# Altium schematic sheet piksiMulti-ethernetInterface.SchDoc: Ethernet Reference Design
size Tabloid; ProjectTitle: 600-00094; ProjectRevision: B; DrawnBy: Shyam R Thillainathan; Organization: Swift Navigation; Address1: 650 Townsend St; Address2: Suite 410; Address3: San Francisco; Address4: CA 94103; DocumentNumber: 600-000XX; Revision: REV A; SheetNumber: 1; SheetTotal: 1
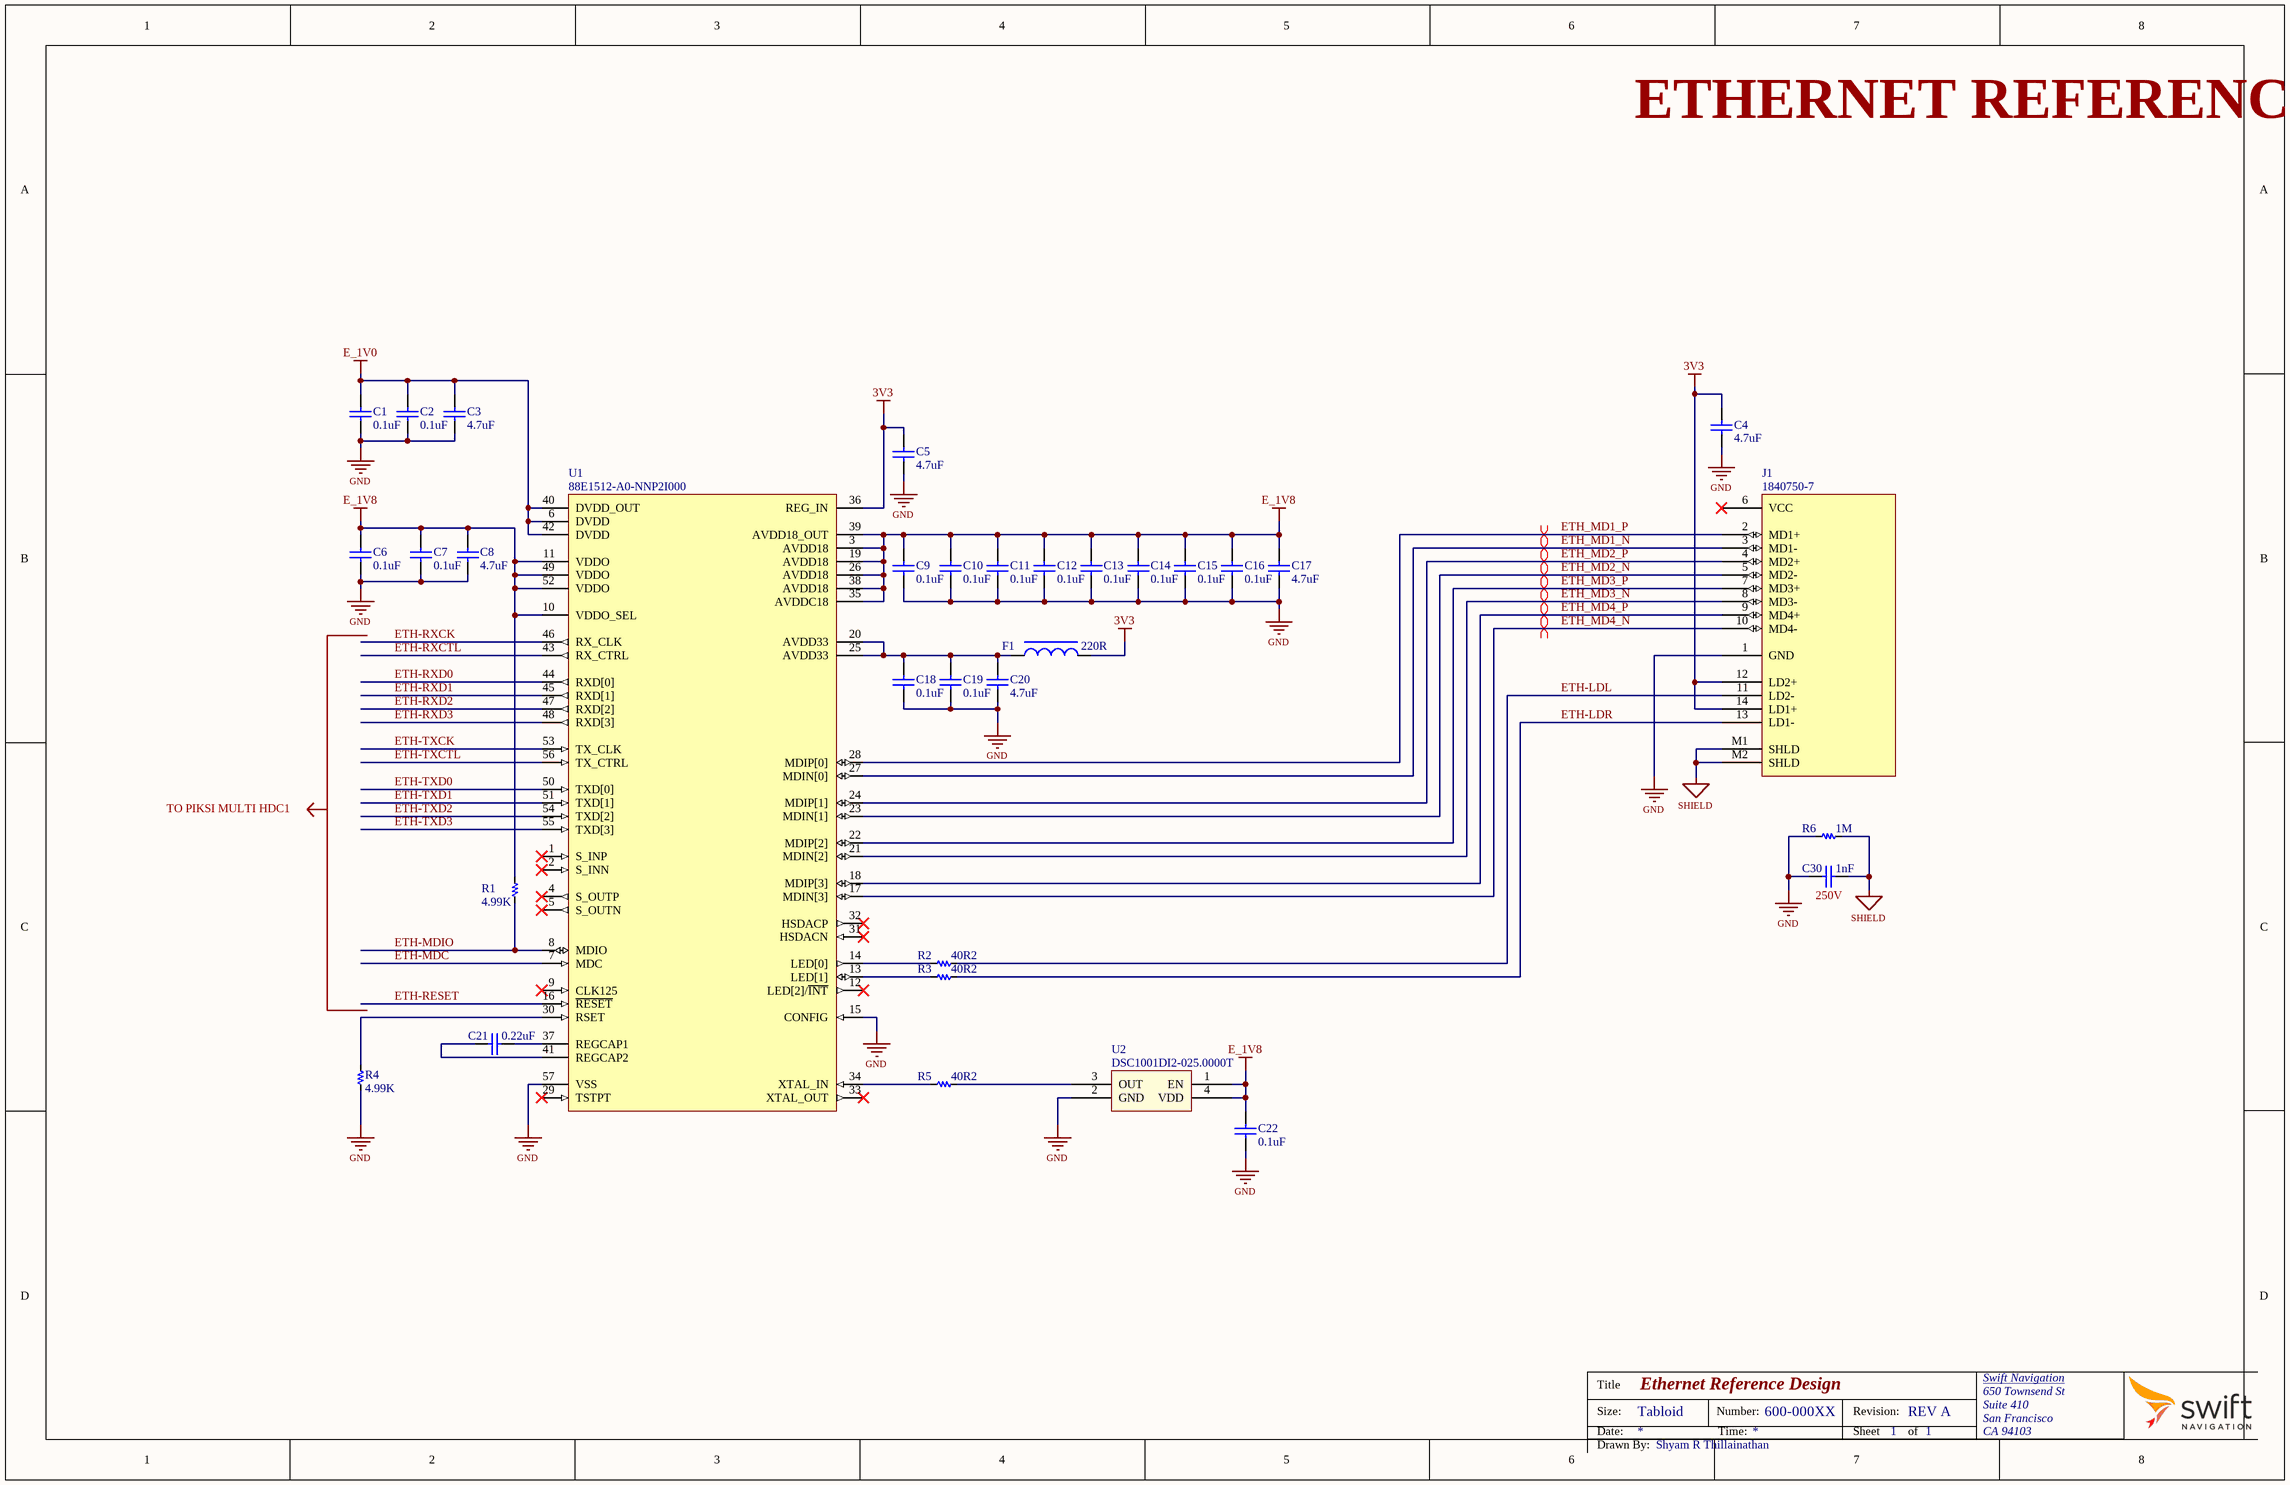
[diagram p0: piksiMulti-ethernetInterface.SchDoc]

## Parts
C1  value 0.1uF
C2  value 0.1uF
C3  value 4.7uF
C4  value 4.7uF
C5  value 4.7uF
C6  value 0.1uF
C7  value 0.1uF
C8  value 4.7uF
C9  value 0.1uF
C10  value 0.1uF
C11  value 0.1uF
C12  value 0.1uF
C13  value 0.1uF
C14  value 0.1uF
C15  value 0.1uF
C16  value 0.1uF
C17  value 4.7uF
C18  value 0.1uF
C19  value 0.1uF
C20  value 4.7uF
C21  value 0.22uF
C22  value 0.1uF
C30  value 1nF
F1  value 220R  [0805]  (hidden comment: IND)
J1  1840750-7
R1  value 4.99K
R2  value 40R2
R3  value 40R2
R4  value 4.99K
R5  value 40R2
R6  value 1M
U1  88E1512-A0-NNP2I000  [QFN56]
U2  DSC1001DI2-025.0000T

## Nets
3V3: C4.2 C5.2 F1.2 J1.12(LD2+) J1.14(LD1+) U1.36(REG_IN)
E_1V0: C1.2 C2.2 C3.2 U1.6(DVDD) U1.40(DVDD_OUT) U1.42(DVDD)
E_1V8: C6.2 C7.2 C8.2 C9.2 C10.2 C11.2 C12.2 C13.2 C14.2 C15.2 C16.2 C17.2 C22.2 R1.1 U1.3(AVDD18) U1.10(VDDO_SEL) U1.11(VDDO) U1.19(AVDD18) U1.26(AVDD18) U1.35(AVDDC18) U1.38(AVDD18) U1.39(AVDD18_OUT) U1.49(VDDO) U1.52(VDDO) U2.1(EN) U2.4(VDD)
GND: C1.1 C2.1 C3.1 C4.1 C5.1 C6.1 C7.1 C8.1 C9.1 C10.1 C11.1 C12.1 C13.1 C14.1 C15.1 C16.1 C17.1 C18.1 C19.1 C20.1 C22.1 C30.2 J1.1(GND) R4.2 R6.1 U1.15(CONFIG) U1.57(VSS) U2.2(GND)
SHIELD: C30.1 J1.M1(SHLD) J1.M2(SHLD) R6.2
ETH-LDL: J1.11(LD2-) R2.2
ETH-LDR: J1.13(LD1-) R3.2
ETH-MDC: U1.7(MDC)
ETH-MDIO: R1.2 U1.8(MDIO)
ETH-RESET: U1.16(~{RESET})
ETH-RXCK: U1.46(RX_CLK)
ETH-RXCTL: U1.43(RX_CTRL)
ETH-RXD0: U1.44(RXD[0])
ETH-RXD1: U1.45(RXD[1])
ETH-RXD2: U1.47(RXD[2])
ETH-RXD3: U1.48(RXD[3])
ETH-TXCK: U1.53(TX_CLK)
ETH-TXCTL: U1.56(TX_CTRL)
ETH-TXD0: U1.50(TXD[0])
ETH-TXD1: U1.51(TXD[1])
ETH-TXD2: U1.54(TXD[2])
ETH-TXD3: U1.55(TXD[3])
ETH_MD1_N: J1.3(MD1-) U1.27(MDIN[0])
ETH_MD1_P: J1.2(MD1+) U1.28(MDIP[0])
ETH_MD2_N: J1.5(MD2-) U1.23(MDIN[1])
ETH_MD2_P: J1.4(MD2+) U1.24(MDIP[1])
ETH_MD3_N: J1.8(MD3-) U1.21(MDIN[2])
ETH_MD3_P: J1.7(MD3+) U1.22(MDIP[2])
ETH_MD4_N: J1.10(MD4-) U1.17(MDIN[3])
ETH_MD4_P: J1.9(MD4+) U1.18(MDIP[3])
NetC18_2: C18.2 C19.2 C20.2 F1.1 U1.20(AVDD33) U1.25(AVDD33)
NetC21_1: C21.1 U1.37(REGCAP1)
NetC21_2: C21.2 U1.41(REGCAP2)
NetR2_1: R2.1 U1.14(LED[0])
NetR3_1: R3.1 U1.13(LED[1])
NetR4_1: R4.1 U1.30(RSET)
NetR5_1: R5.1 U1.34(XTAL_IN)
NetR5_2: R5.2 U2.3(OUT)

Not connected (* = marked no-connect by the designer): J1 6(VCC)*; U1 1(S_INP)* 2(S_INN)* 4(S_OUTP)* 5(S_OUTN)* 9(CLK125)* 12(LED[2]/~{INT})* 29(TSTPT)* 31(HSDACN)* 32(HSDACP)* 33(XTAL_OUT)*

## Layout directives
differential pair: ETH_MD1_N, ETH_MD1_P, ETH_MD2_N, ETH_MD2_P, ETH_MD3_N, ETH_MD3_P, ETH_MD4_N, ETH_MD4_P

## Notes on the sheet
- ETHERNET REFERENCE DESIGN
- TO PIKSI MULTI HDC1
- (near C30) 250V

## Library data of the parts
C1 C2 C6 C7 C9-C16 C18 C19 C22 C30 = CMP-1034-01793-1: CAP CER 0.1UF 50V X7R 0402; Manufacturer Part Number: GCM155R71H104KE02J; Manufacturer: MURATA; Max Reflow Temperature: +260°C; PCB Footprint: C0402
C3-C5 C8 C17 C20 = CMP-1034-01793-1: CAP CER 4.7UF 10V X5R 0402; Manufacturer Part Number: GRM155R61A475MEAAD; Manufacturer: MURATA; Max Reflow Temperature: +260°C; PCB Footprint: C0402
C21 = CMP-1034-01793-1: CAP CER 0.22UF 10V X5R 0402; Manufacturer Part Number: CL05A224KP5NNNC; Manufacturer: SAMSUNG; Max Reflow Temperature: +260°C; PCB Footprint: C0402
F1 = IND: FERRITE BEAD 220 OHM 0805 1LN; Manufacturer: MURATA; Manufacturer Part Number: BLM21PG221SN1D; Max Reflow Temperature: +260°C; PCB Footprint: F0805
J1 = 1840750-7: Conn RJ-45 F 8 POS 2.54mm Solder RA Thru-Hole 8 Terminal 1 Port; Manufacturer: Bel TRP; Shielding: Shielded; Connector Type: RJ45; Gender: Female; Number of Ports: 1; Direction: Up; Number of Positions Loaded: 8
R1 R4 = RES: RES SMD 4.99K OHM 1% 1/16W 0402; Manufacturer Part Number: RC0402FR-074K99L; Manufacturer: YAGEO; Max Reflow Temperature: +260°C; PCB Footprint: R0402
R2 R3 R5 R6 = RES: RES SMD 40.2 OHM 1% 1/16W 0402; Manufacturer Part Number: RC0402FR-0740R2L; Manufacturer: YAGEO; Max Reflow Temperature: +260°C; PCB Footprint: R0402
U1 = Marvell 88E1512: Integrated 10/100/1000 Mbps Energy Efficient Ethernet Tranceiver
U2 = DSC1001DI1: MEMS OSC XO 25.0000MHZ CMOS SMD; Manufacturer: MICROCHIP; Max Reflow Temperature: +260°C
